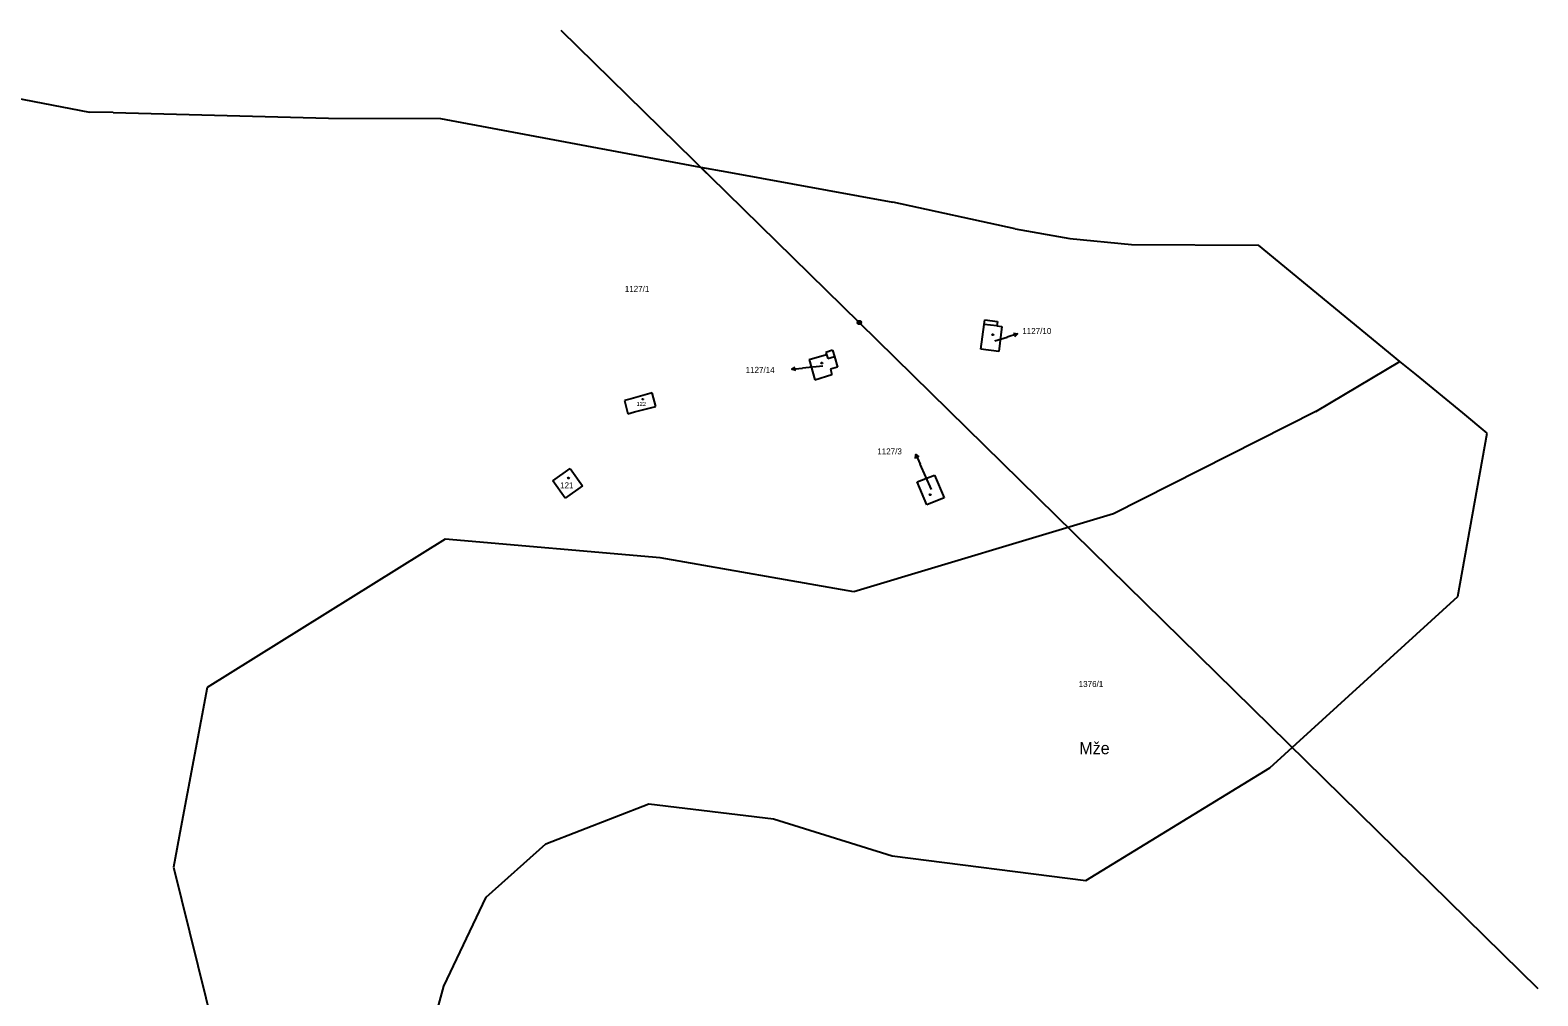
# Model space of a CAD drawing. Extents: x -852001 to -842497, y -1063614 to -1052182.
# Drawn here: x -842923.7 to -842497.1, y -1061301.6 to -1061028.3 of the extents above; entities that cross this region are included whole.
import ezdxf

# ---------------------------------------------------------------- set-up
doc = ezdxf.new("R2010")
doc.units = 0
for name, color, linetype in [('Default', 7, 'Continuous'), ('KN_HRANICE', 7, 'Continuous'), ('KN_KULTURY', 7, 'Continuous'), ('KN_PARCELY', 7, 'Continuous'), ('KN_SLUCKY', 7, 'Continuous'), ('KN_VEDENI', 7, 'Continuous')]:
    doc.layers.add(name, color=color, linetype=linetype)

# ---------------------------------------------------------------- blocks, each defined once
blk = doc.blocks.new('10292')
at = {"layer": 'Default'}
blk.add_line((0, 3), (0, 0), dxfattribs=at)
blk.add_lwpolyline([(-0.5, 2), (0, 3), (0.5, 2)], dxfattribs=at)
blk = doc.blocks.new('402')
at = {"layer": 'Default'}
blk.add_lwpolyline([(0.09, 0.15), (0.18, 0), (0.09, -0.15), (-0.09, -0.15), (-0.18, 0), (-0.09, 0.15), (0.09, 0.15)], dxfattribs=at)
blk = doc.blocks.new('601')
at = {"layer": 'Default'}
blk.add_lwpolyline([(-0.15, 0.48), (0.16, 0.48), (0.41, 0.3), (0.51, 0.01), (0.41, -0.28), (0.16, -0.46), (-0.15, -0.46), (-0.4, -0.28), (-0.5, 0.01), (-0.4, 0.3), (-0.15, 0.48), (-0.12, 0.44), (0.12, 0.44), (0.28, 0.36), (-0.28, 0.36), (-0.36, 0.28), (0.36, 0.28), (0.36, 0.2), (-0.36, 0.2), (-0.4, 0.12), (0.4, 0.12), (0.44, 0.04), (-0.44, 0.04), (-0.44, -0.04), (0.44, -0.04), (0.41, -0.12), (-0.4, -0.12), (-0.39, -0.2), (0.42, -0.2), (0.37, -0.28), (-0.35, -0.28), (-0.27, -0.36), (0.29, -0.36), (0.18, -0.44), (-0.16, -0.44)], dxfattribs=at)

msp = doc.modelspace()

# ---------------------------------------------------------------- linework, layer by layer
at = {"layer": 'KN_HRANICE'}
for p, q in [((-842952.56, -1061042.8), (-842906.85, -1061051.49)), ((-842952.56, -1061042.8), (-842906.85, -1061051.49)), ((-842900.18, -1061051.66), (-842906.85, -1061051.49)), ((-842900.18, -1061051.66), (-842906.85, -1061051.49)), ((-842900.18, -1061051.66), (-842839.32, -1061053.21)), ((-842900.18, -1061051.66), (-842839.32, -1061053.21)), ((-842839.32, -1061053.21), (-842807.56, -1061053.32)), ((-842839.32, -1061053.21), (-842807.56, -1061053.32)), ((-842807.56, -1061053.32), (-842734.03, -1061067.06)), ((-842807.56, -1061053.32), (-842734.03, -1061067.06)), ((-842734.03, -1061067.06), (-842726.61, -1061068.45)), ((-842734.03, -1061067.06), (-842726.61, -1061068.45)), ((-842726.61, -1061068.45), (-842679.6, -1061077.04)), ((-842726.61, -1061068.45), (-842679.6, -1061077.04)), ((-842644.97, -1061084.55), (-842679.6, -1061077.04)), ((-842644.97, -1061084.55), (-842679.6, -1061077.04)), ((-842644.97, -1061084.55), (-842629.5, -1061087.24)), ((-842644.97, -1061084.55), (-842629.5, -1061087.24)), ((-842629.5, -1061087.24), (-842612.1, -1061088.96)), ((-842629.5, -1061087.24), (-842612.1, -1061088.96)), ((-842612.1, -1061088.96), (-842576.15, -1061089.17)), ((-842612.1, -1061088.96), (-842576.15, -1061089.17)), ((-842536.15, -1061122.04), (-842576.15, -1061089.17)), ((-842536.15, -1061122.04), (-842576.15, -1061089.17)), ((-842653.8, -1061111.59), (-842653.64, -1061110.3)), ((-842653.8, -1061111.59), (-842653.64, -1061110.3)), ((-842653.64, -1061110.3), (-842650.05, -1061110.77)), ((-842653.64, -1061110.3), (-842650.05, -1061110.77)), ((-842654.7, -1061118.58), (-842653.8, -1061111.59)), ((-842654.7, -1061118.58), (-842653.8, -1061111.59)), ((-842650.05, -1061110.77), (-842650.21, -1061112.02)), ((-842650.05, -1061110.77), (-842650.21, -1061112.02)), ((-842650.21, -1061112.02), (-842648.77, -1061112.18)), ((-842650.21, -1061112.02), (-842648.77, -1061112.18)), ((-842648.77, -1061112.18), (-842649.65, -1061119.23)), ((-842648.77, -1061112.18), (-842649.65, -1061119.23)), ((-842696.68, -1061118.91), (-842698.58, -1061119.54)), ((-842696.68, -1061118.91), (-842698.58, -1061119.54)), ((-842696.68, -1061118.91), (-842696.16, -1061120.67)), ((-842696.68, -1061118.91), (-842696.16, -1061120.67)), ((-842649.65, -1061119.23), (-842654.7, -1061118.58)), ((-842649.65, -1061119.23), (-842654.7, -1061118.58)), ((-842703.25, -1061121.5), (-842698.41, -1061120.06)), ((-842703.25, -1061121.5), (-842698.41, -1061120.06)), ((-842703.25, -1061121.5), (-842701.68, -1061127.28)), ((-842703.25, -1061121.5), (-842701.68, -1061127.28)), ((-842698.58, -1061119.54), (-842698.41, -1061120.06)), ((-842698.58, -1061119.54), (-842698.41, -1061120.06)), ((-842696.16, -1061120.67), (-842695.3, -1061123.68)), ((-842696.16, -1061120.67), (-842695.3, -1061123.68)), ((-842559.99, -1061136.21), (-842536.15, -1061122.04)), ((-842559.99, -1061136.21), (-842536.15, -1061122.04)), ((-842531.48, -1061125.88), (-842536.15, -1061122.04)), ((-842531.48, -1061125.88), (-842536.15, -1061122.04)), ((-842701.68, -1061127.28), (-842696.84, -1061125.75)), ((-842701.68, -1061127.28), (-842696.84, -1061125.75)), ((-842695.3, -1061123.68), (-842697.29, -1061124.28)), ((-842695.3, -1061123.68), (-842697.29, -1061124.28)), ((-842697.29, -1061124.28), (-842696.84, -1061125.75)), ((-842697.29, -1061124.28), (-842696.84, -1061125.75)), ((-842518.38, -1061136.63), (-842531.48, -1061125.88)), ((-842518.38, -1061136.63), (-842531.48, -1061125.88)), ((-842747.69, -1061130.99), (-842753.68, -1061132.66)), ((-842747.69, -1061130.99), (-842753.68, -1061132.66)), ((-842746.68, -1061134.77), (-842747.69, -1061130.99)), ((-842746.68, -1061134.77), (-842747.69, -1061130.99)), ((-842753.68, -1061132.66), (-842755.57, -1061133.14)), ((-842753.68, -1061132.66), (-842755.57, -1061133.14)), ((-842755.57, -1061133.14), (-842754.55, -1061136.9)), ((-842755.57, -1061133.14), (-842754.55, -1061136.9)), ((-842752.69, -1061136.37), (-842746.68, -1061134.77)), ((-842752.69, -1061136.37), (-842746.68, -1061134.77)), ((-842754.55, -1061136.9), (-842752.69, -1061136.37)), ((-842754.55, -1061136.9), (-842752.69, -1061136.37)), ((-842559.99, -1061136.21), (-842617.22, -1061165.23)), ((-842559.99, -1061136.21), (-842617.22, -1061165.23)), ((-842511.52, -1061142.39), (-842518.38, -1061136.63)), ((-842511.52, -1061142.39), (-842518.38, -1061136.63)), ((-842519.78, -1061188.53), (-842511.52, -1061142.39)), ((-842519.78, -1061188.53), (-842511.52, -1061142.39)), ((-842775.77, -1061155.83), (-842770.91, -1061152.37)), ((-842775.77, -1061155.83), (-842770.91, -1061152.37)), ((-842770.91, -1061152.37), (-842767.41, -1061157.28)), ((-842770.91, -1061152.37), (-842767.41, -1061157.28)), ((-842772.29, -1061160.77), (-842775.77, -1061155.83)), ((-842772.29, -1061160.77), (-842775.77, -1061155.83)), ((-842767.41, -1061157.28), (-842772.29, -1061160.77)), ((-842767.41, -1061157.28), (-842772.29, -1061160.77)), ((-842672.72, -1061156.17), (-842667.86, -1061154.21)), ((-842672.72, -1061156.17), (-842667.86, -1061154.21)), ((-842669.97, -1061162.64), (-842672.72, -1061156.17)), ((-842669.97, -1061162.64), (-842672.72, -1061156.17)), ((-842667.86, -1061154.21), (-842665.14, -1061160.63)), ((-842667.86, -1061154.21), (-842665.14, -1061160.63)), ((-842665.14, -1061160.63), (-842669.97, -1061162.64)), ((-842665.14, -1061160.63), (-842669.97, -1061162.64)), ((-842617.22, -1061165.23), (-842690.67, -1061187.22)), ((-842617.22, -1061165.23), (-842690.67, -1061187.22)), ((-842806.3, -1061172.33), (-842873.56, -1061214.35)), ((-842806.3, -1061172.33), (-842873.56, -1061214.35)), ((-842745.43, -1061177.6), (-842806.3, -1061172.33)), ((-842745.43, -1061177.6), (-842806.3, -1061172.33)), ((-842690.67, -1061187.22), (-842745.43, -1061177.6)), ((-842690.67, -1061187.22), (-842745.43, -1061177.6)), ((-842572.93, -1061237.1), (-842519.78, -1061188.53)), ((-842572.93, -1061237.1), (-842519.78, -1061188.53)), ((-842873.56, -1061214.35), (-842881.05, -1061253.98)), ((-842873.56, -1061214.35), (-842881.05, -1061253.98)), ((-842624.99, -1061268.91), (-842572.93, -1061237.1)), ((-842624.99, -1061268.91), (-842572.93, -1061237.1)), ((-842777.82, -1061258.6), (-842748.65, -1061247.24)), ((-842777.82, -1061258.6), (-842748.65, -1061247.24)), ((-842748.65, -1061247.24), (-842713.35, -1061251.5)), ((-842748.65, -1061247.24), (-842713.35, -1061251.5)), ((-842881.05, -1061253.98), (-842883.17, -1061265.17)), ((-842881.05, -1061253.98), (-842883.17, -1061265.17)), ((-842713.35, -1061251.5), (-842679.84, -1061261.98)), ((-842713.35, -1061251.5), (-842679.84, -1061261.98)), ((-842794.63, -1061273.61), (-842777.82, -1061258.6)), ((-842794.63, -1061273.61), (-842777.82, -1061258.6)), ((-842679.84, -1061261.98), (-842624.99, -1061268.91)), ((-842679.84, -1061261.98), (-842624.99, -1061268.91)), ((-842883.17, -1061265.17), (-842866.58, -1061331.78)), ((-842883.17, -1061265.17), (-842866.58, -1061331.78)), ((-842806.61, -1061298.85), (-842794.63, -1061273.61)), ((-842806.61, -1061298.85), (-842794.63, -1061273.61)), ((-842822.75, -1061357.48), (-842806.61, -1061298.85)), ((-842822.75, -1061357.48), (-842806.61, -1061298.85))]:
    msp.add_line(p, q, dxfattribs=at)
at = {"layer": 'KN_PARCELY'}
for p, q in [((-842650.72, -1061116.19), (-842647.26, -1061115.16)), ((-842650.72, -1061116.19), (-842647.26, -1061115.16)), ((-842699.38, -1061123.37), (-842705.17, -1061123.96)), ((-842699.38, -1061123.37), (-842705.17, -1061123.96)), ((-842668.64, -1061158.33), (-842671.91, -1061151.1)), ((-842668.64, -1061158.33), (-842671.91, -1061151.1))]:
    msp.add_line(p, q, dxfattribs=at)
at = {"layer": 'KN_SLUCKY'}
for p, q in [((-842650.21, -1061112.02), (-842653.8, -1061111.59)), ((-842650.21, -1061112.02), (-842653.8, -1061111.59)), ((-842698.41, -1061120.06), (-842698.03, -1061121.26)), ((-842698.41, -1061120.06), (-842698.03, -1061121.26)), ((-842698.03, -1061121.26), (-842696.16, -1061120.67)), ((-842698.03, -1061121.26), (-842696.16, -1061120.67))]:
    msp.add_line(p, q, dxfattribs=at)
at = {"layer": 'KN_VEDENI'}
for p, q in [((-842773.58, -1061028.33), (-842689.12, -1061111.06)), ((-842773.58, -1061028.33), (-842689.12, -1061111.06)), ((-842734.03, -1061067.06), (-842730.41, -1061070.61)), ((-842734.03, -1061067.06), (-842730.41, -1061070.61)), ((-842689.12, -1061111.06), (-842497.14, -1061299.53)), ((-842689.12, -1061111.06), (-842497.14, -1061299.53))]:
    msp.add_line(p, q, dxfattribs=at)

# ---------------------------------------------------------------- block references
at = {"layer": 'KN_KULTURY'}
for p in [(-842651.33, -1061114.48), (-842651.33, -1061114.48), (-842699.74, -1061122.48), (-842699.74, -1061122.48), (-842771.37, -1061155.06), (-842771.37, -1061155.06), (-842669.09, -1061159.78), (-842669.09, -1061159.78)]:
    msp.add_blockref('402', p, dxfattribs=at)
at = {"layer": 'KN_KULTURY', "xscale": 0.67, "yscale": 0.67}
msp.add_blockref('402', (-842750.34, -1061132.73), dxfattribs=at)
msp.add_blockref('402', (-842750.34, -1061132.73), dxfattribs=at)
at = {"layer": 'KN_PARCELY'}
for p, rotation in [((-842647.26, -1061115.16), -73.349215), ((-842647.26, -1061115.16), -73.349215), ((-842705.17, -1061123.96), 95.79854300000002), ((-842705.17, -1061123.96), 95.79854300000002), ((-842671.91, -1061151.1), 24.350706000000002), ((-842671.91, -1061151.1), 24.350706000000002)]:
    msp.add_blockref('10292', p, dxfattribs=dict(at, rotation=rotation))
at = {"layer": 'KN_VEDENI'}
msp.add_blockref('601', (-842689.12, -1061111.06), dxfattribs=at)
msp.add_blockref('601', (-842689.12, -1061111.06), dxfattribs=at)

# ---------------------------------------------------------------- texts
at = {"layer": 'KN_PARCELY'}
for s, height, p in [('1127/1', 1.7, (-842755.46, -1061102.38)), ('1127/1', 1.7, (-842755.46, -1061102.38)), ('1127/10', 1.7, (-842643, -1061114.3)), ('1127/10', 1.7, (-842643, -1061114.3)), ('1127/10', 0.1, (-842651.07, -1061116.19)), ('1127/10', 0.1, (-842651.07, -1061116.19)), ('1127/14', 0.1, (-842699.73, -1061123.37)), ('1127/14', 0.1, (-842699.73, -1061123.37)), ('1127/14', 1.7, (-842721.27, -1061125.3)), ('1127/14', 1.7, (-842721.27, -1061125.3)), ('122', 1.14, (-842752.11, -1061134.65)), ('122', 1.14, (-842752.11, -1061134.65)), ('1127/3', 1.7, (-842684.02, -1061148.37)), ('1127/3', 1.7, (-842684.02, -1061148.37)), ('121', 1.7, (-842773.76, -1061157.97)), ('121', 1.7, (-842773.76, -1061157.97)), ('1127/3', 0.1, (-842668.94, -1061158.33)), ('1127/3', 0.1, (-842668.94, -1061158.33)), ('1376/1', 1.7, (-842627.04, -1061214.19)), ('1376/1', 1.7, (-842627.04, -1061214.19)), ('Mže', 3.4, (-842626.87, -1061233.19)), ('Mže', 3.4, (-842626.87, -1061233.19))]:
    msp.add_text(s, height=height, dxfattribs=at).set_placement(p)

doc.saveas('drawing.dxf')
